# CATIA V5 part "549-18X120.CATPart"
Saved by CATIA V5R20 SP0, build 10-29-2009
Part number: 549-18X120
Definition: NONE
Nomenclature: 549-18X120
Source: Unknown
Description: 549-18X120
Bounding box of the stored display mesh (mm): x 0 to 120, y -10.5 to 10.5, z -10.5 to 10.5
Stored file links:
  C:\Users\Utente\Desktop\IO LAVORO\3D X SITO CF\X SITO\PLASTICA\549\549-18X120.CATPart
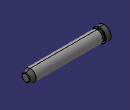
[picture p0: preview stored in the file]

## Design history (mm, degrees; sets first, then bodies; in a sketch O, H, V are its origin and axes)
Body1 "549-18X120" (main body)
  Solid1: solid without history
